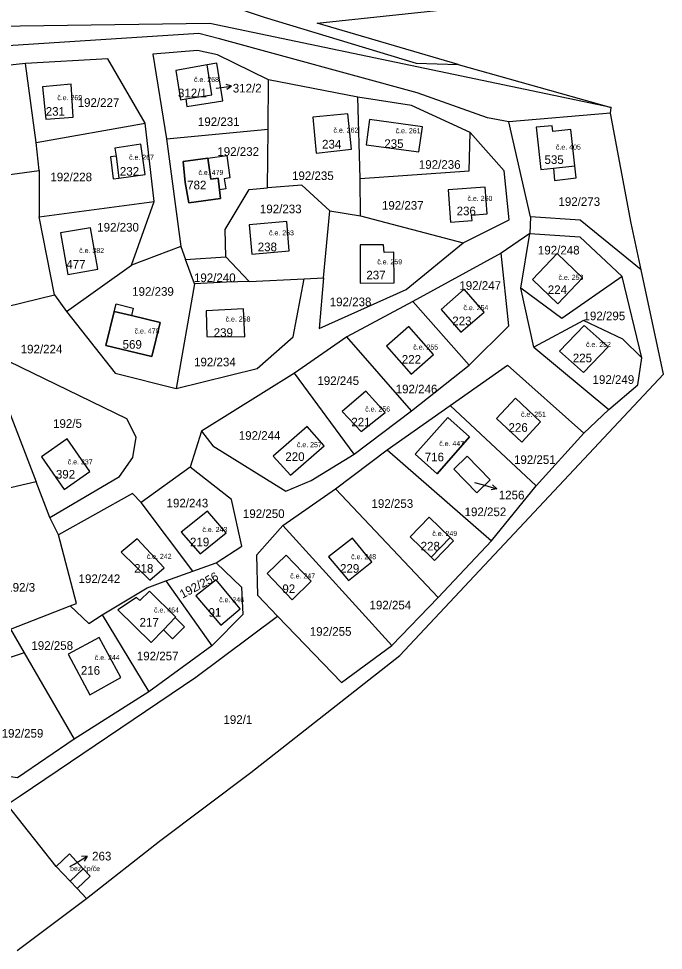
# Model space of a CAD drawing. Extents: x -887272 to -880188, y -1026687 to -1021896.
# Drawn here: x -882082.9 to -881955.8, y -1024195.4 to -1024011.9 of the extents above; entities that cross this region are included whole.
import ezdxf

# ---------------------------------------------------------------- set-up
doc = ezdxf.new("R2010")
doc.units = 0
for name, color, linetype in [('Definiční body', 7, 'Continuous'), ('Hranice parcel', 7, 'Continuous'), ('Parcelní čísla', 7, 'Continuous'), ('Polygon budovy', 7, 'Continuous'), ('Pop  PČ popisy', 7, 'Continuous'), ('Vnitřní kresba', 7, 'Continuous')]:
    doc.layers.add(name, color=color, linetype=linetype)

msp = doc.modelspace()

# ---------------------------------------------------------------- linework, layer by layer
at = {"layer": 'Hranice parcel'}
for p, q in [((-882081.54, -1024020.75), (-882098.51, -1024022.43)), ((-882079.39, -1024036.31), (-882081.54, -1024020.75)), ((-881996.26, -1024020.9), (-881966.06, -1024029.4)), ((-882033.72, -1024033.65), (-882033.62, -1024023.94)), ((-882015.99, -1024027.37), (-882033.62, -1024023.94)), ((-882015.56, -1024043.36), (-882015.99, -1024027.37)), ((-881966.19, -1024030.49), (-881986.24, -1024032.2)), ((-881966.19, -1024030.49), (-881966.06, -1024029.4)), ((-882079.39, -1024036.31), (-882057.94, -1024032.5)), ((-882056.17, -1024047.94), (-882057.94, -1024032.5)), ((-881986.24, -1024032.2), (-881990.45, -1024031.46)), ((-881981.99, -1024050.95), (-881986.24, -1024032.2)), ((-882053.75, -1024035.57), (-882033.72, -1024033.65)), ((-882033.85, -1024045.24), (-882033.72, -1024033.65)), ((-882078.8, -1024041.81), (-882079.39, -1024036.31)), ((-882053.75, -1024035.57), (-882050.91, -1024056.8)), ((-882096.15, -1024044.11), (-882078.8, -1024041.81)), ((-882078.8, -1024041.81), (-882078.85, -1024050.92)), ((-882015.47, -1024050.7), (-882015.56, -1024043.36)), ((-882078.85, -1024050.92), (-882056.17, -1024047.94)), ((-882060.66, -1024060.43), (-882056.17, -1024047.94)), ((-882075.8, -1024066.27), (-882078.85, -1024050.92)), ((-882022.76, -1024062.97), (-882021.57, -1024049.73)), ((-882021.57, -1024049.73), (-882015.47, -1024050.7)), ((-882015.47, -1024050.7), (-881995.27, -1024056.03)), ((-881981.99, -1024050.95), (-881982.11, -1024054.18)), ((-881982.11, -1024054.18), (-881987.76, -1024058.08)), ((-881983.9, -1024065.01), (-881982.11, -1024054.18)), ((-882050.91, -1024056.8), (-882060.66, -1024060.43)), ((-882050.91, -1024056.8), (-882049.97, -1024059.33)), ((-881987.76, -1024058.08), (-882005.18, -1024067.63)), ((-882073.41, -1024069.57), (-882060.66, -1024060.43)), ((-882049.97, -1024059.33), (-882042.04, -1024058.8)), ((-882048.19, -1024064.15), (-882049.97, -1024059.33)), ((-882042.04, -1024058.8), (-882037.42, -1024063.65)), ((-882048.19, -1024064.15), (-882051.8, -1024084.74)), ((-882037.42, -1024063.65), (-882026.59, -1024063.12)), ((-882026.59, -1024063.12), (-882022.76, -1024062.97)), ((-881960.02, -1024078.69), (-881963.91, -1024062.69)), ((-881981.34, -1024076.58), (-881983.9, -1024065.01)), ((-882075.8, -1024066.27), (-882073.41, -1024069.57)), ((-882005.18, -1024067.63), (-882018.18, -1024074.54)), ((-881994.05, -1024080.12), (-882005.18, -1024067.63)), ((-882018.18, -1024074.54), (-882028.47, -1024081.74)), ((-882005.43, -1024089.12), (-882018.18, -1024074.54)), ((-881981.34, -1024076.58), (-881966.56, -1024088.9)), ((-882089.45, -1024077.18), (-882079.4, -1024103.11)), ((-882005.43, -1024089.12), (-881994.05, -1024080.12)), ((-882028.47, -1024081.74), (-882046.83, -1024093.16)), ((-882016.75, -1024097.7), (-882028.47, -1024081.74)), ((-882016.75, -1024097.7), (-882005.43, -1024089.12)), ((-882010.27, -1024096.8), (-881997.83, -1024088.08)), ((-881997.83, -1024088.08), (-881980.86, -1024103.94)), ((-881971.46, -1024093.55), (-881966.56, -1024088.9)), ((-882046.83, -1024093.16), (-882049.06, -1024100.21)), ((-881980.86, -1024103.94), (-881971.46, -1024093.55)), ((-882020.4, -1024104.47), (-882010.27, -1024096.8)), ((-882010.27, -1024096.8), (-881989.7, -1024114.76)), ((-882049.06, -1024100.21), (-882058.69, -1024107.22)), ((-882079.4, -1024103.11), (-882097.11, -1024107.19)), ((-882076.7, -1024110.12), (-882079.4, -1024103.11)), ((-882030.77, -1024111.71), (-882020.4, -1024104.47)), ((-882020.4, -1024104.47), (-882000.18, -1024125.91)), ((-881989.7, -1024114.76), (-881980.86, -1024103.94)), ((-882048.55, -1024120.72), (-882058.69, -1024107.22)), ((-882075.03, -1024113.55), (-882076.7, -1024110.12)), ((-882030.77, -1024111.71), (-882009.31, -1024135.36)), ((-882000.18, -1024125.91), (-881989.7, -1024114.76)), ((-882048.55, -1024120.72), (-882043.95, -1024119.08)), ((-882053.87, -1024122.61), (-882048.55, -1024120.72)), ((-882053.87, -1024122.61), (-882044.82, -1024135.41)), ((-882009.31, -1024135.36), (-882000.18, -1024125.91)), ((-882084.49, -1024132.15), (-882072.69, -1024127.57)), ((-882066.44, -1024129.33), (-882057.24, -1024144.48)), ((-882084.49, -1024132.15), (-882081.79, -1024136.83)), ((-882044.82, -1024135.41), (-882057.24, -1024144.48)), ((-882081.79, -1024136.83), (-882101.79, -1024143.4)), ((-882081.79, -1024136.83), (-882071.96, -1024153.83)), ((-882057.24, -1024144.48), (-882071.96, -1024153.83)), ((-882085.12, -1024166.68), (-882082.59, -1024164.97)), ((-882075.46, -1024178.88), (-882085.12, -1024166.68)), ((-882069.52, -1024185.2), (-882071.31, -1024183.21)), ((-882083.16, -1024195.4), (-882069.52, -1024185.2))]:
    msp.add_line(p, q, dxfattribs=at)
for points in [[(-882138.72, -1024014.17), (-882125.55, -1024011.67), (-882085.96, -1024002.08), (-882063.17, -1024001.87), (-882034.49, -1024011.62), (-882004.55, -1024020.66), (-881996.26, -1024020.9)], [(-881996.26, -1024020.9), (-882024.01, -1024012.79), (-881998.04, -1024010.02)], [(-881966.06, -1024029.4), (-882045.19, -1024012.84), (-882138.72, -1024014.17)], [(-881990.45, -1024031.46), (-882004.32, -1024026.5), (-882043.3, -1024015.89), (-882047.34, -1024014.83), (-882128.82, -1024020.06), (-882138.81, -1024017.01), (-882141.19, -1024015.69)], [(-882033.62, -1024023.94), (-882043.68, -1024019.01), (-882047.61, -1024018.17), (-882056.43, -1024018.92), (-882053.75, -1024035.57)], [(-882057.94, -1024032.5), (-882065.31, -1024019.82), (-882081.54, -1024020.75)], [(-882045.7, -1024021.02), (-882051.92, -1024022.08), (-882051, -1024027.88), (-882049.91, -1024027.71)], [(-882049.91, -1024027.71), (-882049.7, -1024029.2), (-882042.62, -1024028.08), (-882043.79, -1024020.69), (-882045.7, -1024021.02)], [(-882049.91, -1024027.71), (-882044.78, -1024026.88), (-882045.7, -1024021.02)], [(-882077.52, -1024031.66), (-882072.14, -1024031.28), (-882072.52, -1024024.8), (-882078.14, -1024025.32), (-882077.52, -1024031.66)], [(-881993.88, -1024034.29), (-882005.45, -1024028.99), (-882015.99, -1024027.37)], [(-882017.26, -1024037.58), (-882017.98, -1024030.61), (-882024.89, -1024031.33), (-882024.21, -1024038.4), (-882017.26, -1024037.58)], [(-881960.2, -1024061.34), (-881962.15, -1024052.19), (-881966.19, -1024030.49)], [(-882003.3, -1024033.17), (-882013.7, -1024031.77), (-882014.37, -1024036.72), (-882003.97, -1024038.12), (-882003.3, -1024033.17)], [(-881977.48, -1024041.35), (-881977.24, -1024043.74), (-881973.01, -1024043.27), (-881973.27, -1024040.88), (-881974.06, -1024033.73), (-881977.61, -1024034.12), (-881977.74, -1024032.98), (-881980.86, -1024033.3), (-881980.74, -1024034.47), (-881979.94, -1024041.62), (-881977.48, -1024041.35)], [(-882015.56, -1024043.36), (-881994.07, -1024041.9), (-881993.88, -1024034.29)], [(-881995.27, -1024056.03), (-881986.22, -1024051.53), (-881987.19, -1024041.89), (-881993.88, -1024034.29)], [(-882063.94, -1024037.39), (-882063.65, -1024038.98), (-882064.79, -1024039.13), (-882064.24, -1024043.45), (-882063.1, -1024043.29), (-882057.94, -1024042.58), (-882058.8, -1024036.64), (-882063.94, -1024037.39)], [(-882050.43, -1024040.02), (-882045.57, -1024039.37), (-882041.87, -1024038.87), (-882041.23, -1024043.27), (-882042.37, -1024043.46), (-882042.05, -1024045.4), (-882043.29, -1024045.59), (-882043.08, -1024047.35), (-882049.32, -1024048.18)], [(-882049.32, -1024048.18), (-882050.05, -1024044.19), (-882050.43, -1024040.02)], [(-882042.04, -1024058.8), (-882042.17, -1024053.44), (-882037.46, -1024045.53), (-882033.85, -1024045.24)], [(-882021.57, -1024049.73), (-882027.06, -1024044.68), (-882033.85, -1024045.24)], [(-881998.24, -1024045.59), (-881997.75, -1024051.95), (-881993.51, -1024051.65), (-881993.59, -1024050.57), (-881990.55, -1024050.36), (-881990.92, -1024045.08), (-881998.24, -1024045.59)], [(-882116.91, -1024046.86), (-882109.08, -1024060.61), (-882091.67, -1024070.17), (-882075.8, -1024066.27)], [(-881960.2, -1024061.34), (-881972.17, -1024051.58), (-881981.99, -1024050.95)], [(-882067.25, -1024061.24), (-882068.72, -1024053.09), (-882074.61, -1024054.11), (-882073.18, -1024062.27), (-882067.25, -1024061.24)], [(-882036.91, -1024058.26), (-882029.54, -1024057.62), (-882030.04, -1024051.84), (-882037.41, -1024052.48), (-882036.91, -1024058.26)], [(-881982.11, -1024054.18), (-881972.27, -1024054.88), (-881963.91, -1024062.69)], [(-882022.76, -1024062.97), (-882023.66, -1024072.94), (-882006.48, -1024065.27), (-881995.27, -1024056.03)], [(-882008.92, -1024057.9), (-882010.82, -1024057.94), (-882010.93, -1024056.44), (-882015.56, -1024056.46), (-882015.54, -1024063.98), (-882008.84, -1024063.9), (-882008.92, -1024057.9)], [(-881994.05, -1024080.12), (-881986.25, -1024072.41), (-881987.76, -1024058.08)], [(-881976.63, -1024068.04), (-881971.73, -1024062.95), (-881976.71, -1024058.15), (-881981.62, -1024063.24), (-881976.63, -1024068.04)], [(-882069.52, -1024185.2), (-882055.12, -1024173.92), (-882037.1, -1024160.36), (-882007.72, -1024137.32), (-881955.8, -1024081.94), (-881960.2, -1024061.34)], [(-882051.8, -1024084.74), (-882035.87, -1024080.78), (-882028.78, -1024074.57), (-882026.59, -1024063.12)], [(-882037.42, -1024063.65), (-882041.92, -1024063.81), (-882048.19, -1024064.15)], [(-881963.91, -1024062.69), (-881975.83, -1024070.92), (-881983.9, -1024065.01)], [(-881999.62, -1024069.16), (-881995.69, -1024073.66), (-881991.13, -1024069.68), (-881995.06, -1024065.18), (-881999.62, -1024069.16)], [(-882073.41, -1024069.57), (-882063.84, -1024081.75), (-882051.8, -1024084.74)], [(-882054.97, -1024071.72), (-882056.61, -1024078.46), (-882065.67, -1024076.24), (-882064.02, -1024069.56), (-882063.62, -1024068.09), (-882060.29, -1024068.89), (-882060.66, -1024070.36), (-882054.97, -1024071.72)], [(-882045.9, -1024069.46), (-882045.8, -1024074.52), (-882038.28, -1024074.56), (-882038.58, -1024069.08), (-882045.9, -1024069.46)], [(-881960.02, -1024078.69), (-881963.78, -1024075), (-881971.54, -1024071.37), (-881981.34, -1024076.58)], [(-882005.51, -1024081.91), (-882001.11, -1024078.05), (-882005.97, -1024072.51), (-882010.35, -1024076.39), (-882005.51, -1024081.91)], [(-881966.68, -1024076.52), (-881971.4, -1024072.34), (-881976.26, -1024077.38), (-881971.57, -1024081.6), (-881966.68, -1024076.52)], [(-882060.37, -1024098.33), (-882059.72, -1024094.32), (-882061.57, -1024090.71), (-882089.45, -1024077.18)], [(-881966.56, -1024088.9), (-881960.82, -1024084.04), (-881960.02, -1024078.69)], [(-881997.83, -1024088.08), (-881986.52, -1024080.15), (-881971.46, -1024093.55)], [(-882010.64, -1024089.46), (-882014.46, -1024085.24), (-882019.12, -1024089.3), (-882015.36, -1024093.24), (-882010.64, -1024089.46)], [(-881980.04, -1024091.29), (-881984.97, -1024086.62), (-881988.71, -1024090.67), (-881983.71, -1024095.29), (-881980.04, -1024091.29)], [(-882000.36, -1024101.52), (-882004.71, -1024097.69), (-881998.28, -1024090.47), (-881994, -1024094.28), (-882000.36, -1024101.52)], [(-882046.83, -1024093.16), (-882044.58, -1024096.03), (-882030.18, -1024104.96), (-882025.22, -1024102.86), (-882016.75, -1024097.7)], [(-882032.69, -1024098.05), (-882029.27, -1024101.79), (-882022.64, -1024096.04), (-882026.02, -1024092.19), (-882032.69, -1024098.05)], [(-882073.92, -1024104.65), (-882068.81, -1024101.06), (-882073.28, -1024094.64), (-882078.36, -1024098.17), (-882073.92, -1024104.65)], [(-882076.7, -1024110.12), (-882062.98, -1024102.04), (-882060.37, -1024098.33)], [(-881997.1, -1024100.62), (-881994.49, -1024098.07), (-881989.95, -1024102.73), (-881992.54, -1024105.27), (-881997.1, -1024100.62)], [(-882043.95, -1024119.08), (-882038.89, -1024115.77), (-882040.92, -1024106.59), (-882049.06, -1024100.21)], [(-882058.69, -1024107.22), (-882060.43, -1024105.42), (-882075.03, -1024113.55)], [(-882041.98, -1024113.14), (-882045.68, -1024108.92), (-882050.86, -1024113.02), (-882047.1, -1024117.32), (-882041.98, -1024113.14)], [(-882031.85, -1024129.56), (-882035.72, -1024125.54), (-882035.9, -1024117.48), (-882030.77, -1024111.71)], [(-881997.83, -1024114.08), (-882001.97, -1024110.09), (-882005.72, -1024113.98), (-882001.58, -1024117.97), (-882000.93, -1024118.6), (-881997.18, -1024114.71), (-881997.83, -1024114.08)], [(-882072.69, -1024127.57), (-882071.47, -1024127.11), (-882075.03, -1024113.55)], [(-882057, -1024122.52), (-882054.16, -1024120.06), (-882059.48, -1024114.34), (-882062.66, -1024116.98), (-882057, -1024122.52)], [(-882013.29, -1024118.9), (-882017.07, -1024114.2), (-882021.79, -1024117.9), (-882017.86, -1024122.57), (-882013.29, -1024118.9)], [(-882043.95, -1024119.08), (-882038.95, -1024123.84), (-882038.66, -1024129.26), (-882044.82, -1024135.41)], [(-882025.21, -1024122.66), (-882030.14, -1024117.57), (-882033.88, -1024121.19), (-882028.94, -1024126.36), (-882025.21, -1024122.66)], [(-882066.44, -1024129.33), (-882057.57, -1024123.99), (-882053.87, -1024122.61)], [(-882043.04, -1024131.32), (-882039.18, -1024128.14), (-882043.94, -1024122.44), (-882047.93, -1024125.57), (-882043.04, -1024131.32)], [(-882050.19, -1024131.68), (-882052, -1024129.85), (-882051.91, -1024129.76), (-882057.08, -1024124.67), (-882058.97, -1024126.52), (-882059.63, -1024125.89), (-882063.31, -1024128.32), (-882056.76, -1024134.74), (-882054.35, -1024132.27), (-882052.57, -1024134.05), (-882050.19, -1024131.68)], [(-882072.69, -1024127.57), (-882069.05, -1024131.01), (-882066.44, -1024129.33)], [(-882082.59, -1024164.97), (-882047.94, -1024141.57), (-882031.85, -1024129.56)], [(-882031.85, -1024129.56), (-882019.27, -1024142.62), (-882009.31, -1024135.36)], [(-882073.08, -1024137.08), (-882068.84, -1024145.04), (-882062.71, -1024141.64), (-882066.97, -1024133.76), (-882073.08, -1024137.08)], [(-882071.96, -1024153.83), (-882083.08, -1024161.39), (-882086.23, -1024160.99), (-882101.79, -1024143.4)], [(-882071.31, -1024183.21), (-882068.78, -1024180.79), (-882070.14, -1024179.33), (-882072.86, -1024176.4), (-882075.46, -1024178.88)], [(-882075.46, -1024178.88), (-882072.69, -1024181.77), (-882071.31, -1024183.21)]]:
    msp.add_lwpolyline(points, dxfattribs=at)
at = {"layer": 'Polygon budovy'}
for points in [[(-882045.7, -1024021.02), (-882051.92, -1024022.08), (-882051, -1024027.88), (-882049.91, -1024027.71), (-882044.78, -1024026.88)], [(-882078.14, -1024025.32), (-882077.52, -1024031.66), (-882072.14, -1024031.28), (-882072.52, -1024024.8)], [(-882017.98, -1024030.61), (-882024.89, -1024031.33), (-882024.21, -1024038.4), (-882017.26, -1024037.58)], [(-882003.3, -1024033.17), (-882013.7, -1024031.77), (-882014.37, -1024036.72), (-882003.97, -1024038.12)], [(-881974.06, -1024033.73), (-881977.61, -1024034.12), (-881977.74, -1024032.98), (-881980.86, -1024033.3), (-881980.74, -1024034.47), (-881979.94, -1024041.62), (-881977.48, -1024041.35), (-881973.27, -1024040.88)], [(-882063.1, -1024043.29), (-882057.94, -1024042.58), (-882058.8, -1024036.64), (-882063.94, -1024037.39), (-882063.65, -1024038.98)], [(-882050.43, -1024040.02), (-882050.05, -1024044.19), (-882049.32, -1024048.18), (-882043.08, -1024047.35), (-882043.29, -1024045.59), (-882043.55, -1024043.33), (-882045.02, -1024043.53), (-882045.57, -1024039.37)], [(-881990.92, -1024045.08), (-881998.24, -1024045.59), (-881997.75, -1024051.95), (-881993.51, -1024051.65), (-881993.59, -1024050.57), (-881990.55, -1024050.36)], [(-882074.61, -1024054.11), (-882073.18, -1024062.27), (-882067.25, -1024061.24), (-882068.72, -1024053.09)], [(-882029.54, -1024057.62), (-882030.04, -1024051.84), (-882037.41, -1024052.48), (-882036.91, -1024058.26)], [(-882010.82, -1024057.94), (-882010.93, -1024056.44), (-882015.56, -1024056.46), (-882015.54, -1024063.98), (-882008.84, -1024063.9), (-882008.92, -1024057.9)], [(-881971.73, -1024062.95), (-881976.71, -1024058.15), (-881981.62, -1024063.24), (-881976.63, -1024068.04)], [(-881991.13, -1024069.68), (-881995.06, -1024065.18), (-881999.62, -1024069.16), (-881995.69, -1024073.66)], [(-882065.67, -1024076.24), (-882056.61, -1024078.46), (-882054.97, -1024071.72), (-882060.66, -1024070.36), (-882064.02, -1024069.56)], [(-882045.9, -1024069.46), (-882045.8, -1024074.52), (-882038.28, -1024074.56), (-882038.58, -1024069.08)], [(-882005.51, -1024081.91), (-882001.11, -1024078.05), (-882005.97, -1024072.51), (-882010.35, -1024076.39)], [(-881966.68, -1024076.52), (-881971.4, -1024072.34), (-881976.26, -1024077.38), (-881971.57, -1024081.6)], [(-882014.46, -1024085.24), (-882019.12, -1024089.3), (-882015.36, -1024093.24), (-882010.64, -1024089.46)], [(-881983.71, -1024095.29), (-881980.04, -1024091.29), (-881984.97, -1024086.62), (-881988.71, -1024090.67)], [(-882004.71, -1024097.69), (-882000.36, -1024101.52), (-881994, -1024094.28), (-881998.28, -1024090.47)], [(-882022.64, -1024096.04), (-882026.02, -1024092.19), (-882032.69, -1024098.05), (-882029.27, -1024101.79)], [(-882073.28, -1024094.64), (-882078.36, -1024098.17), (-882073.92, -1024104.65), (-882068.81, -1024101.06)], [(-882045.68, -1024108.92), (-882050.86, -1024113.02), (-882047.1, -1024117.32), (-882041.98, -1024113.14)], [(-882005.72, -1024113.98), (-882001.58, -1024117.97), (-881997.83, -1024114.08), (-882001.97, -1024110.09)], [(-882059.48, -1024114.34), (-882062.66, -1024116.98), (-882057, -1024122.52), (-882054.16, -1024120.06)], [(-882017.86, -1024122.57), (-882013.29, -1024118.9), (-882017.07, -1024114.2), (-882021.79, -1024117.9)], [(-882033.88, -1024121.19), (-882028.94, -1024126.36), (-882025.21, -1024122.66), (-882030.14, -1024117.57)], [(-882043.94, -1024122.44), (-882047.93, -1024125.57), (-882043.04, -1024131.32), (-882039.18, -1024128.14)], [(-882063.31, -1024128.32), (-882056.76, -1024134.74), (-882054.35, -1024132.27), (-882052, -1024129.85), (-882051.91, -1024129.76), (-882057.08, -1024124.67), (-882058.97, -1024126.52), (-882059.63, -1024125.89)], [(-882066.97, -1024133.76), (-882073.08, -1024137.08), (-882068.84, -1024145.04), (-882062.71, -1024141.64)], [(-882075.46, -1024178.88), (-882072.69, -1024181.77), (-882070.14, -1024179.33), (-882072.86, -1024176.4)]]:
    msp.add_lwpolyline(points, close=True, dxfattribs=at)
at = {"layer": 'Pop  PČ popisy'}
for p, q in [((-882043.93, -1024025.62), (-882043.89, -1024025.61)), ((-882043.89, -1024025.61), (-882040.92, -1024025.19)), ((-882040.92, -1024025.19), (-882041.98, -1024024.84)), ((-882040.92, -1024025.19), (-882041.84, -1024025.83)), ((-881993, -1024103.25), (-881991.51, -1024103.67)), ((-881991.51, -1024103.67), (-881988.62, -1024104.5)), ((-881988.62, -1024104.5), (-881989.73, -1024104.7)), ((-881988.62, -1024104.5), (-881989.45, -1024103.74)), ((-882071.95, -1024178.4), (-882069.38, -1024176.85)), ((-882069.38, -1024176.85), (-882070.49, -1024176.94)), ((-882069.38, -1024176.85), (-882069.98, -1024177.8)), ((-882072.76, -1024178.9), (-882071.95, -1024178.4))]:
    msp.add_line(p, q, dxfattribs=at)
at = {"layer": 'Vnitřní kresba'}
for p, q in [((-882063.65, -1024038.98), (-882063.1, -1024043.29)), ((-882045.57, -1024039.37), (-882045.02, -1024043.53)), ((-881977.48, -1024041.35), (-881973.27, -1024040.88)), ((-882045.02, -1024043.53), (-882043.55, -1024043.33)), ((-882043.55, -1024043.33), (-882043.29, -1024045.59)), ((-882064.02, -1024069.56), (-882060.66, -1024070.36)), ((-881997.83, -1024114.08), (-882001.58, -1024117.97)), ((-882052, -1024129.85), (-882054.35, -1024132.27)), ((-882072.69, -1024181.77), (-882070.14, -1024179.33))]:
    msp.add_line(p, q, dxfattribs=at)

# ---------------------------------------------------------------- texts
at = {"layer": 'Definiční body'}
for s, p in [('č.e. 268', (-882048.31, -1024024.37)), ('č.e. 269', (-882075.26, -1024027.95)), ('č.e. 262', (-882020.82, -1024034.35)), ('č.e. 261', (-882008.57, -1024034.47)), ('č.e. 405', (-881976.98, -1024037.69)), ('č.e. 267', (-882061.11, -1024039.69)), ('č.e. 479', (-882047.43, -1024042.69)), ('č.e. 260', (-881994.41, -1024047.8)), ('č.e. 263', (-882033.53, -1024054.57)), ('č.e. 382', (-882070.94, -1024058.06)), ('č.e. 259', (-882012.2, -1024060.28)), ('č.e. 253', (-881976.47, -1024063.35)), ('č.e. 254', (-881995.21, -1024069.31)), ('č.e. 258', (-882042.09, -1024071.56)), ('č.e. 470', (-882060.03, -1024073.91)), ('č.e. 255', (-882005.1, -1024077.08)), ('č.e. 252', (-881971.05, -1024076.56)), ('č.e. 256', (-882014.57, -1024089.28)), ('č.e. 251', (-881983.86, -1024090.32)), ('č.e. 257', (-882028.03, -1024096.3)), ('č.e. 447', (-881999.98, -1024096.08)), ('č.e. 237', (-882073.2, -1024099.68)), ('č.e. 243', (-882046.65, -1024113.01)), ('č.e. 249', (-882001.35, -1024113.79)), ('č.e. 242', (-882057.64, -1024118.3)), ('č.e. 248', (-882017.34, -1024118.36)), ('č.e. 247', (-882029.35, -1024122.15)), ('č.e. 246', (-882043.35, -1024126.84)), ('č.e. 464', (-882056.19, -1024128.86)), ('č.e. 244', (-882067.87, -1024138.23)), ('bez čp/če', (-882072.74, -1024179.79))]:
    msp.add_text(s, height=1, dxfattribs=at).set_placement(p)
at = {"layer": 'Parcelní čísla'}
for s, p in [('312/1', (-882051.47, -1024027.38)), ('312/2', (-882040.67, -1024026.44)), ('192/227', (-882071.24, -1024029.27)), ('231', (-882077.53, -1024031.01)), ('192/231', (-882047.54, -1024033.04)), ('234', (-882023.07, -1024037.47)), ('235', (-882010.8, -1024037.36)), ('192/232', (-882043.71, -1024038.92)), ('192/236', (-882003.99, -1024041.47)), ('535', (-881979.23, -1024040.51)), ('192/228', (-882076.62, -1024043.93)), ('232', (-882062.92, -1024042.82)), ('192/235', (-882028.99, -1024043.68)), ('782', (-882049.66, -1024045.51)), ('192/273', (-881976.48, -1024048.78)), ('192/233', (-882035.32, -1024050.22)), ('192/237', (-882011.27, -1024049.52)), ('236', (-881996.55, -1024050.62)), ('192/230', (-882067.38, -1024053.83)), ('238', (-882035.75, -1024057.7)), ('192/248', (-881980.53, -1024058.34)), ('477', (-882073.48, -1024061.13)), ('192/240', (-882048.32, -1024063.78)), ('237', (-882014.34, -1024063.25)), ('192/247', (-881996.01, -1024065.3)), ('192/239', (-882060.5, -1024066.48)), ('224', (-881978.58, -1024066.14)), ('192/238', (-882021.56, -1024068.53)), ('192/295', (-881971.54, -1024071.29)), ('223', (-881997.41, -1024072.28)), ('239', (-882044.43, -1024074.58)), ('569', (-882062.38, -1024076.9)), ('192/224', (-882082.47, -1024077.83)), ('192/234', (-882048.3, -1024080.37)), ('222', (-882007.35, -1024079.85)), ('225', (-881973.65, -1024079.58)), ('192/245', (-882023.99, -1024084.05)), ('192/249', (-881969.76, -1024083.83)), ('192/246', (-882008.56, -1024085.69)), ('192/5', (-882076.09, -1024092.49)), ('221', (-882017.3, -1024092.2)), ('226', (-881986.33, -1024093.27)), ('192/244', (-882039.48, -1024094.84)), ('220', (-882030.31, -1024099.01)), ('716', (-882002.83, -1024099.08)), ('192/251', (-881985.24, -1024099.6)), ('392', (-882075.53, -1024102.48)), ('192/243', (-882053.72, -1024108.16)), ('1256', (-881988.24, -1024106.57)), ('192/253', (-882013.33, -1024108.25)), ('192/252', (-881994.98, -1024109.88)), ('192/250', (-882038.67, -1024110.24)), ('219', (-882049.1, -1024115.82)), ('228', (-882003.64, -1024116.64)), ('218', (-882060.11, -1024121.03)), ('229', (-882019.53, -1024121.03)), ('192/242', (-882071.06, -1024123.06)), ('192/3', (-882085.31, -1024124.75)), ('92', (-882030.89, -1024125.03)), ('192/254', (-882013.72, -1024128.24)), ('91', (-882045.45, -1024129.69)), ('217', (-882059.04, -1024131.63)), ('192/255', (-882025.49, -1024133.44)), ('192/258', (-882080.36, -1024136.21)), ('192/257', (-882059.58, -1024138.28)), ('216', (-882070.61, -1024141.12)), ('192/1', (-882042.51, -1024150.8)), ('192/259', (-882086.22, -1024153.5)), ('263', (-882068.39, -1024177.69))]:
    msp.add_text(s, height=1.7, dxfattribs=at).set_placement(p)
msp.add_text('192/256', height=1.7, rotation=28, dxfattribs=at).set_placement((-882050.57, -1024126.14))

doc.saveas('drawing.dxf')
